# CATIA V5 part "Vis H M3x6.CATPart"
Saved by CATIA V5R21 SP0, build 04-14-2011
Part number: Vis H M3x6
Material "Acier": density 7860 kg/m3, Young's modulus 2e+11 Pa, Poisson ratio 0.266, thermal expansion 1.17e-05 1/K
Bounding box of the stored display mesh (mm): x -2.5 to 2.5, y -2.887 to 2.887, z 0 to 8
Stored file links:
  C:\Users\Olivier\Desktop\redaction CATIA (local)\pompe à moteur de ventilation refait\Vis H M3x6.CATPart
  C:\Program Files\Dassault Systemes\B21\win_b64\startup\materials\French\Catalog.CATMaterial
  C:\Program Files\Dassault Systemes\B21\win_b64\resources\graphic\figures\CATIA_EnvironmentMap_Satin_512x512.jpg
  C:\Users\Olivier\Desktop\redaction CATIA (local)\pompe à moteur de ventilation refait\Pompe_a_moteur_de_ventilation.CATProduct
  C:\Users\Olivier\Desktop\redaction CATIA (local)\pompe à moteur de ventilation refait\Ecrou a collerette M5.CATPart
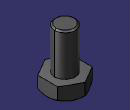
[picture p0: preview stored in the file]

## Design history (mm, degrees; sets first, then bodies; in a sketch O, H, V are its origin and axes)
Body1 (main body), material "Acier"
  Sketch1 on xy-plane, origin (0, 0, 0), H (1, 0, 0), V (0, 1, 0)
    circle A1 centre (0, 0) radius 1.5
    point P1 (2.5, -1.4434)
    point P2 (2.5, 1.4434)
    point P3 (0, 2.8868)
    point P4 (-2.5, 1.4434)
    point P5 (-2.5, -1.4434)
    point P6 (0, -2.8868)
    point P7 (2.5, 0)
    line L1 (2.5, -1.4434) -> (2.5, 1.4434)
    line L2 (2.5, 1.4434) -> (0, 2.8868)
    line L3 (0, 2.8868) -> (-2.5, 1.4434)
    line L4 (-2.5, 1.4434) -> (-2.5, -1.4434)
    line L5 (-2.5, -1.4434) -> (0, -2.8868)
    line L6 (0, -2.8868) -> (2.5, -1.4434)
    construction line L7 (0, 0) -> (2.5, 0)
    construction circle A2 centre (0, 0) radius 2.8868
    construction arc A3 centre (-2.5, -1.4434) radius 2.8868 from (-2.5, 1.4434) to (0, -2.8868) cw
    construction arc A4 centre (2.5, 1.4434) radius 2.8868 from (0, 2.8868) to (2.5, -1.4434) ccw
    distance L1 L4 = 5
    horizontal: L7 H
    coincidence: A2 P1, A2 P2, A2 P3, A2 P4, A2 P5, A2 P6, A3 O, A4 O
    midpoint: P7 L1
  MultiPad1: profile Sketch1, domains (length 2; length 8)
  Sketch2 on yz-plane, origin (0, 0, 0), H (0, 1, 0), V (0, 0, 1)
    line L1 (2.509, 0) -> (2.9319, 0.3605)
    point P1 (2.509, 0)
    line L2 (2.9319, 0.3605) -> (2.9319, 0)
    point P3 (2.9319, 0)
    line L3 (2.9319, 0) -> (2.509, 0)
    coincidence: P1 H, P3 H
    vertical: L2 V
    horizontal: L3 H
  Groove1: profile Sketch2, axis Sketch2.V, angle 360
  Chamfer1: length 0.2, angle 45, on face of MultiPad1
